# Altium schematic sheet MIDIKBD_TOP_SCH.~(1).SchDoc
size A4
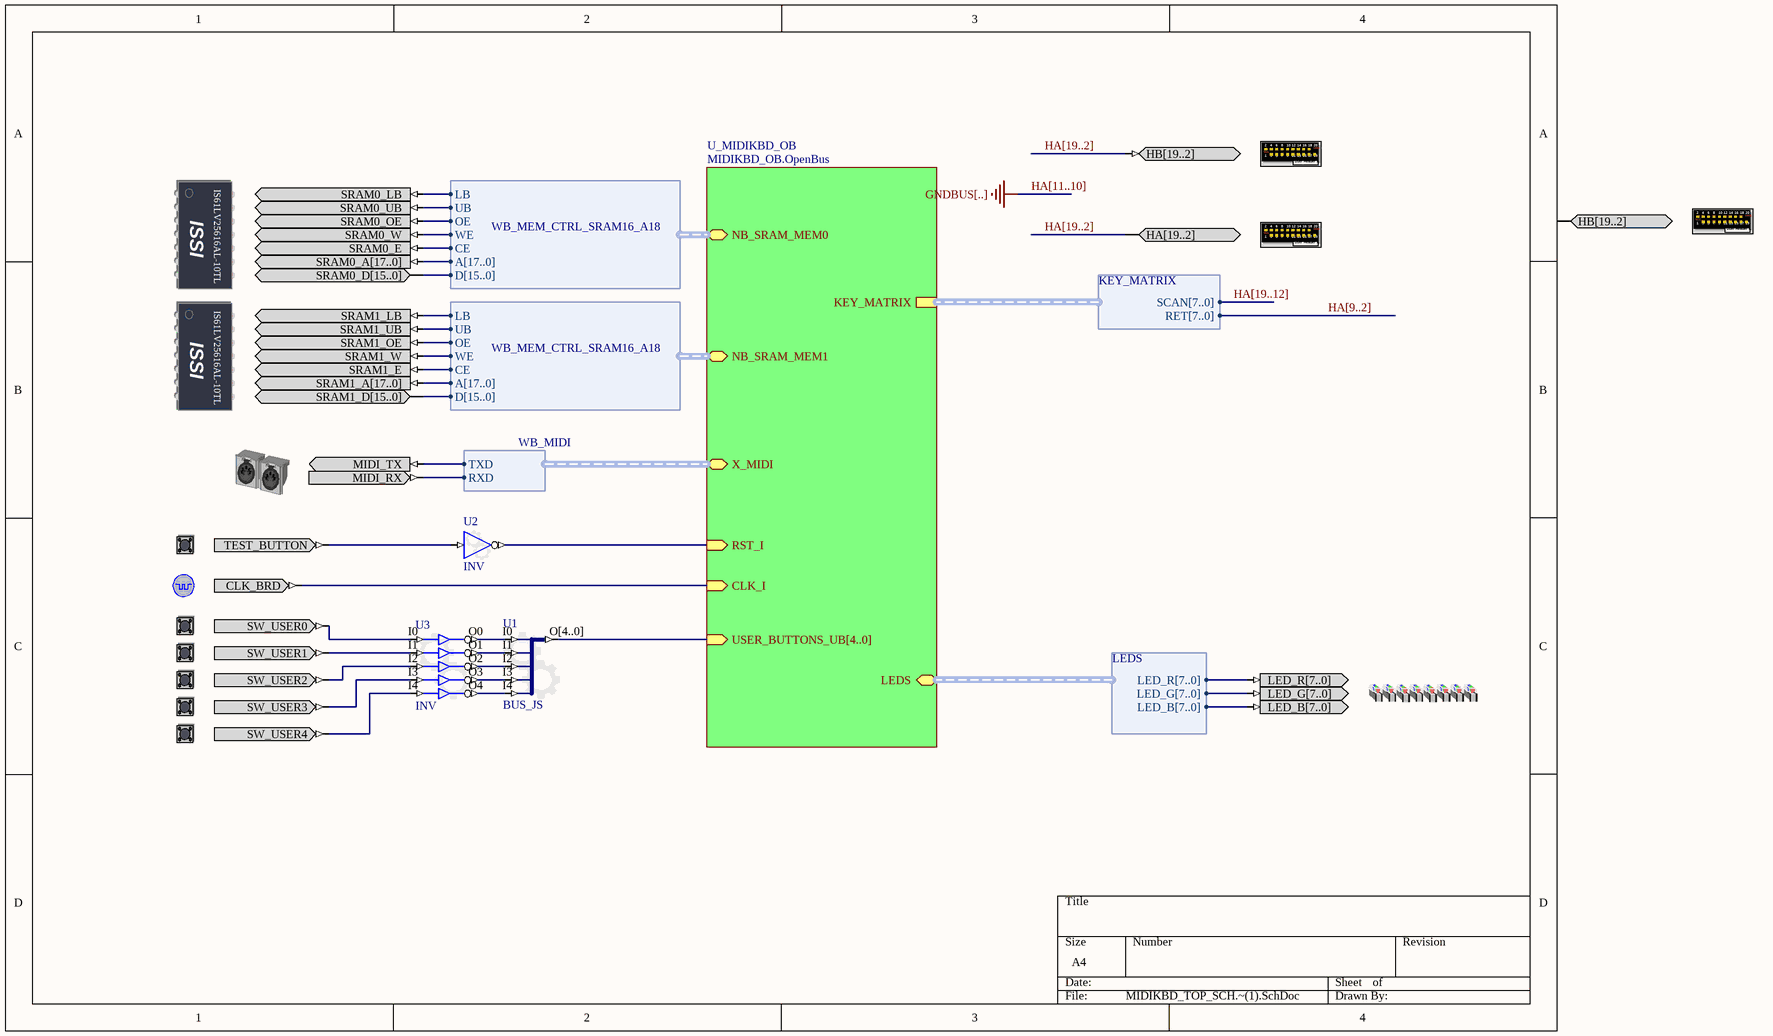
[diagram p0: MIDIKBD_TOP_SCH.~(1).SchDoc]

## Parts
(Parts that share a designator on the sheet are numbered #1, #2 ... from top to bottom, then left to right.)
?#1  USER_HEADER_B  (value not drawn)
?#2  USER_HEADER_B  (value not drawn)
?#3  USER_HEADER_A  (value not drawn)
?#4  SRAM0  (value not drawn)
?#5  SRAM1  (value not drawn)
?#6  MIDI  (value not drawn)
?#7  TEST_BUTTON  (value not drawn)
?#8  CLOCK_BOARD  (value not drawn)
?#9  USER_BUTTON0  (value not drawn)
?#10  USER_BUTTON1  (value not drawn)
?#11  USER_BUTTON2  (value not drawn)
?#12  LEDS_RGB  (value not drawn)
?#13  USER_BUTTON3  (value not drawn)
?#14  USER_BUTTON4  (value not drawn)
U1  BUS_JS
U2  INV
U3  INV

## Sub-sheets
U_MIDIKBD_OB = MIDIKBD_OB.OpenBus: KEY_MATRIX (harness KEY_MATRIX), RST_I (in), CLK_I (in), LEDS (harness LEDS), X_MIDI (harness WB_MIDI), USER_BUTTONS_UB[4..0] (in), NB_SRAM_MEM0 (harness WB_MEM_CTRL_SRAM16_A18), NB_SRAM_MEM1 (harness WB_MEM_CTRL_SRAM16_A18)

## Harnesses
KEY_MATRIX: SCAN[7..0], RET[7..0]
LEDS: LED_R[7..0], LED_G[7..0], LED_B[7..0]
WB_MIDI: RXD, TXD
WB_MEM_CTRL_SRAM16_A18: D[15..0], A[17..0], CE, WE, OE, UB, LB

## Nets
Net?#4_SRAM0_E: ?#4.SRAM0_E ; sheet U_MIDIKBD_OB/NB_SRAM_MEM0.CE
Net?#4_SRAM0_LB: ?#4.SRAM0_LB ; sheet U_MIDIKBD_OB/NB_SRAM_MEM0.LB
Net?#4_SRAM0_OE: ?#4.SRAM0_OE ; sheet U_MIDIKBD_OB/NB_SRAM_MEM0.OE
Net?#4_SRAM0_UB: ?#4.SRAM0_UB ; sheet U_MIDIKBD_OB/NB_SRAM_MEM0.UB
Net?#4_SRAM0_W: ?#4.SRAM0_W ; sheet U_MIDIKBD_OB/NB_SRAM_MEM0.WE
Net?#5_SRAM1_E: ?#5.SRAM1_E ; sheet U_MIDIKBD_OB/NB_SRAM_MEM1.CE
Net?#5_SRAM1_LB: ?#5.SRAM1_LB ; sheet U_MIDIKBD_OB/NB_SRAM_MEM1.LB
Net?#5_SRAM1_OE: ?#5.SRAM1_OE ; sheet U_MIDIKBD_OB/NB_SRAM_MEM1.OE
Net?#5_SRAM1_UB: ?#5.SRAM1_UB ; sheet U_MIDIKBD_OB/NB_SRAM_MEM1.UB
Net?#5_SRAM1_W: ?#5.SRAM1_W ; sheet U_MIDIKBD_OB/NB_SRAM_MEM1.WE
Net?#6_MIDI_RX: ?#6.MIDI_RX ; sheet U_MIDIKBD_OB/X_MIDI.RXD
Net?#6_MIDI_TX: ?#6.MIDI_TX ; sheet U_MIDIKBD_OB/X_MIDI.TXD
Net?#7_TEST_BUTTON: ?#7.TEST_BUTTON U2.I
Net?#8_CLK_BRD: ?#8.CLK_BRD ; sheet U_MIDIKBD_OB/CLK_I
Net?#9_SW_USER0: ?#9.SW_USER0 U3.I0
Net?#10_SW_USER1: ?#10.SW_USER1 U3.I1
Net?#11_SW_USER2: ?#11.SW_USER2 U3.I2
Net?#13_SW_USER3: ?#13.SW_USER3 U3.I3
Net?#14_SW_USER4: ?#14.SW_USER4 U3.I4
NetU1_I0: U1.I0 U3.O0
NetU1_I1: U1.I1 U3.O1
NetU1_I2: U1.I2 U3.O2
NetU1_I3: U1.I3 U3.O3
NetU1_I4: U1.I4 U3.O4
NetU2_O: U2.O ; sheet U_MIDIKBD_OB/RST_I

Not connected (* = marked no-connect by the designer): ?#1 HB[19..2]; ?#2 HB[19..2]; ?#3 HA[19..2]; ?#4 SRAM0_A[17..0] SRAM0_D[15..0]; ?#5 SRAM1_A[17..0] SRAM1_D[15..0]; ?#12 LED_B[7..0] LED_G[7..0] LED_R[7..0]; U1 O[4..0]

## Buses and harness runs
bus HA[9..2]
bus HA[11..10]
bus HA[19..2]
bus HA[19..12]

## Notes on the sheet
- Labels drawn without touching a wire or pin: GNDBUS[..]

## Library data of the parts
?#1 ?#2 = USER_HEADER_B: User Header B; PortComponent: True
?#3 = USER_HEADER_A: User Header A; PortComponent: True
?#4 = SRAM0: Free Static RAM - Daughterboard; PortComponent: True
?#5 = SRAM1: Free Static RAM - Daughterboard; PortComponent: True
?#6 = MIDI: MIDI Connector; PortComponent: True
?#7 = TEST_BUTTON: Test / Reset Button; PortComponent: True
?#8 = CLOCK_BOARD: Global System Clock Supply; PortComponent: True
?#9 = USER_BUTTON0: Generic User Button; PortComponent: True
?#10 = USER_BUTTON1: Generic User Button; PortComponent: True
?#11 = USER_BUTTON2: Generic User Button; PortComponent: True
?#12 = LEDS_RGB: LEDS RGB; PortComponent: True
?#13 = USER_BUTTON3: Generic User Button; PortComponent: True
?#14 = USER_BUTTON4: Generic User Button; PortComponent: True
U1 = BUS_JS: Configurable Bus Joiner/Splitter; ConfiguratorName: GENERIC_BUS_JS; ConfigurationParameters: {}Version[1.1]{}SplitterJoinerType[Joiner]{}SignalCount[5]{}SignalWidth0[1]{}GapBelow0[1000000]{}ConnectionType0[Pin]{}SignalWidth1[1]{}GapBelow1[1000000]{}ConnectionType1[Pin]{}SignalWidth2[1]{}GapBelow2[1000000]{}ConnectionType2[Pin]{}SignalWidth3[1]{}GapBelow3[1000000]{}ConnectionType3[Pin]{}SignalWidth4[1]{}GapBelow4[1000000]{}ConnectionType4[Pin]{}ShowPinNames[True]{}
U2 = INV: Configurable Inverter; ConfigurationParameters: {}Version[1.1]{}SignalCount[1]{}SignalWidth0[1]{}OutputOption0[Inverted]{}EnableMode[None]{}ShowPinNames[False]{}; ConfiguratorName: GENERIC_BUFFER
U3 = INV: Configurable Inverter; ConfigurationParameters: {}Version[1.1]{}SignalCount[5]{}SignalWidth0[1]{}OutputOption0[Inverted]{}SignalWidth1[1]{}OutputOption1[Inverted]{}SignalWidth2[1]{}OutputOption2[Inverted]{}SignalWidth3[1]{}OutputOption3[Inverted]{}SignalWidth4[1]{}OutputOption4[Inverted]{}EnableMode[None]{}ShowPinNames[True]{}; ConfiguratorName: GENERIC_BUFFER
